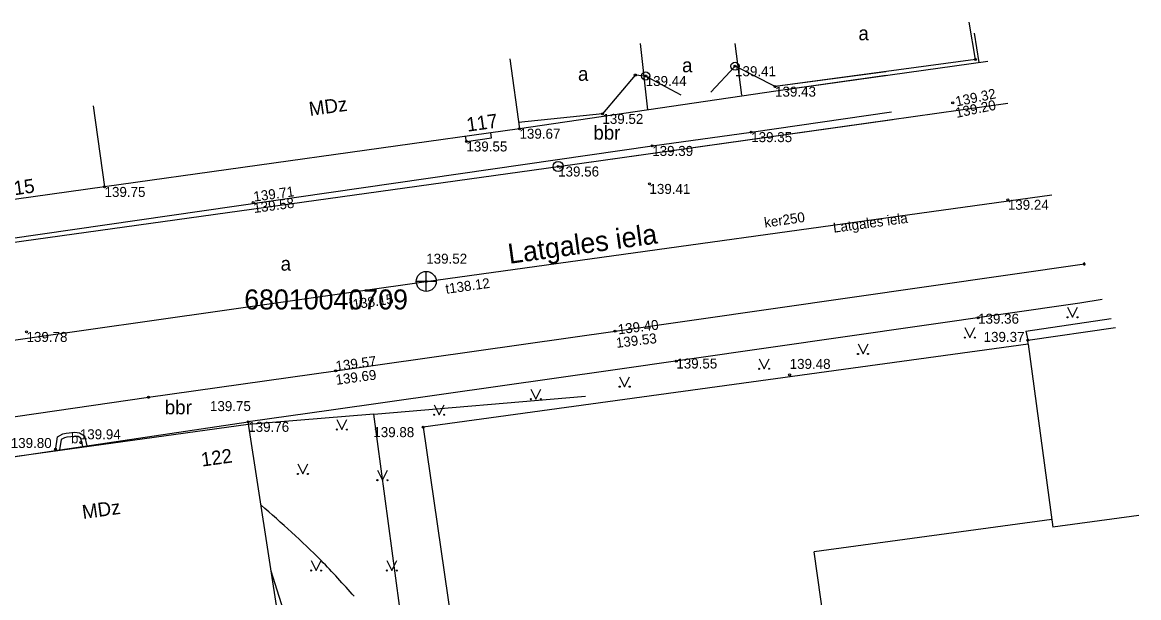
# Model space of a CAD drawing. Extents: x 728848 to 728956, y 273098 to 273185.
# Drawn here: x 728884.3 to 728940.1, y 273155.9 to 273184.7 of the extents above; entities that cross this region are included whole.
import ezdxf

# ---------------------------------------------------------------- set-up
doc = ezdxf.new("R2010")
doc.units = 0
for name, color, linetype in [('BUVE_BDET_####_####_#', 7, 'Continuous'), ('BUVE_BDET_####_TKST_#', 7, 'Continuous'), ('BUVE_EKAS_####_####_#', 7, 'Continuous'), ('BUVE_EKAS_ADRS_TKST_#', 7, 'Continuous'), ('BUVE_EKAS_RAKS_TKST_#', 7, 'Continuous'), ('CELI_CAPM_####_####_#', 7, 'Continuous'), ('CELI_CMAL_####_####_#', 7, 'Continuous'), ('CELI_CSEG_####_TKST_#', 7, 'Continuous'), ('CELI_IELA_####_TKST_#', 7, 'Continuous'), ('ELEK_ELEM_####_####_#', 7, 'Continuous'), ('ELEK_VADV_ZSPR_####_#', 7, 'Continuous'), ('NORB_ELEM_####_####_#', 7, 'Continuous'), ('NORB_ZOGS_ZSTP_####_#', 7, 'Continuous'), ('RELJ_AATZ_####_TKST_#', 7, 'Continuous'), ('RELJ_ELEM_####_####_#', 7, 'Continuous'), ('RELJ_HORZ_RESN_####_#', 7, 'Continuous'), ('ROBZ_KADS_####_TKST_#', 7, 'Continuous'), ('ROBZ_UZMR_####_####_#', 7, 'Continuous'), ('SKAN_ELEM_####_####_#', 7, 'Continuous'), ('SKAN_ELEM_PAST_TKST_#', 7, 'Continuous'), ('SKAN_VADP_PAST_####_#', 7, 'Continuous'), ('SKAN_VADP_PAST_TKST_#', 7, 'Continuous'), ('TERT_ELEM_####_####_#', 7, 'Continuous')]:
    doc.layers.add(name, color=color, linetype=linetype)

msp = doc.modelspace()

# ---------------------------------------------------------------- linework, layer by layer
at = {"layer": 'BUVE_BDET_####_####_#'}
for p, q in [((728907.767, 273178.889), (728907.73, 273179.145)), ((728906.509, 273178.709), (728906.468, 273178.968)), ((728906.509, 273178.709), (728907.767, 273178.889))]:
    msp.add_line(p, q, dxfattribs=at)
for points in [[(728885.974, 273163.262), (728886.081, 273163.935), (728886.346, 273164.087), (728886.515, 273164.125), (728886.941, 273164.169), (728887.184, 273164.149), (728887.422, 273163.993), (728887.535, 273163.494)], [(728887.335, 273163.464), (728887.243, 273163.868), (728887.115, 273163.952), (728886.943, 273163.966), (728886.548, 273163.925), (728886.42, 273163.896), (728886.265, 273163.808), (728886.184, 273163.294)]]:
    msp.add_lwpolyline(points, dxfattribs=at)
at = {"layer": 'BUVE_EKAS_####_####_#'}
for p, q in [((728908.671, 273182.834), (728909.161, 273179.346)), ((728887.858, 273180.487), (728888.427, 273176.436)), ((728909.161, 273179.346), (728888.427, 273176.436)), ((728888.427, 273176.436), (728876.392, 273174.747)), ((728934.555, 273168.77), (728938.942, 273169.413)), ((728934.577, 273168.568), (728904.348, 273164.427)), ((728934.577, 273168.568), (728934.555, 273168.77)), ((728934.577, 273168.568), (728935.813, 273159.42)), ((728880.21, 273162.407), (728895.607, 273164.692)), ((728881.265, 273162.564), (728895.607, 273164.692)), ((728897.893, 273149.784), (728895.607, 273164.692)), ((728904.348, 273164.427), (728910.037, 273125.181)), ((728935.759, 273159.816), (728923.879, 273158.199)), ((728940.1, 273160.003), (728935.813, 273159.42)), ((728928.159, 273127.726), (728923.879, 273158.199))]:
    msp.add_line(p, q, dxfattribs=at)
at = {"layer": 'CELI_CAPM_####_####_#'}
for points in [[(728877.231, 273172.928), (728915.793, 273178.486), (728920.739, 273179.175), (728927.751, 273180.197)], [(728874.692, 273163.616), (728890.623, 273165.918), (728899.975, 273167.245), (728913.935, 273169.231), (728937.385, 273172.585), (728937.418, 273172.59)]]:
    msp.add_lwpolyline(points, dxfattribs=at)
at = {"layer": 'CELI_CMAL_####_####_#'}
msp.add_line((728934.468, 273169.221), (728938.73, 273169.854), dxfattribs=at)
for points in [[(728915.567, 273180.287), (728915.213, 273183.6)], [(728920.275, 273181.023), (728919.945, 273183.6)], [(728932.125, 273182.653), (728931.891, 273184.116)], [(728932.564, 273182.712), (728921.973, 273181.228), (728909.161, 273179.346)], [(728927.488, 273182.001), (728921.973, 273181.228), (728909.161, 273179.346)], [(728938.276, 273170.802), (728937.162, 273170.62), (728913.708, 273167.266), (728899.747, 273165.28), (728895.607, 273164.692)], [(728934.468, 273169.221), (728934.555, 273168.77)]]:
    msp.add_lwpolyline(points, dxfattribs=at)
at = {"layer": 'ELEK_ELEM_####_####_#'}
msp.add_circle((728911.092, 273177.457), 0.25, dxfattribs=at)
at = {"layer": 'ELEK_VADV_ZSPR_####_#'}
for p, q in [((728911.092, 273177.457), (728933.567, 273180.62)), ((728911.092, 273177.457), (728927.807, 273179.81)), ((728880.569, 273173.213), (728911.092, 273177.457)), ((728899.357, 273149.053), (728896.751, 273157.234))]:
    msp.add_line(p, q, dxfattribs=at)
at = {"layer": 'NORB_ELEM_####_####_#'}
for p, q in [((728919.931, 273182.471), (728918.718, 273181.177)), ((728915.467, 273181.981), (728917.23, 273181.048))]:
    msp.add_line(p, q, dxfattribs=at)
for centre in [(728919.931, 273182.471), (728915.467, 273181.981)]:
    msp.add_circle(centre, 0.202, dxfattribs=at)
at = {"layer": 'NORB_ZOGS_ZSTP_####_#'}
for points in [[(728931.95, 273182.807), (728931.628, 273184.665)], [(728931.95, 273182.807), (728921.93, 273181.449), (728919.931, 273182.471)], [(728927.46, 273182.198), (728921.93, 273181.449), (728919.931, 273182.471)], [(728915.467, 273181.981), (728914.949, 273182.03), (728913.303, 273180.087), (728909.117, 273179.656)]]:
    msp.add_lwpolyline(points, dxfattribs=at)
at = {"layer": 'RELJ_ELEM_####_####_#'}
msp.add_line((728937.431, 273172.564), (728937.398, 273172.634), dxfattribs=at)
for centre in [(728919.931, 273182.471), (728931.95, 273182.807), (728914.949, 273182.03), (728915.467, 273181.981), (728921.93, 273181.449), (728930.806, 273180.643), (728913.303, 273180.087), (728909.161, 273179.346), (728920.739, 273179.175), (728906.509, 273178.709), (728915.793, 273178.486), (728911.092, 273177.457), (728888.427, 273176.436), (728915.655, 273176.587), (728933.561, 273175.793), (728895.854, 273175.652), (728904.501, 273171.712), (728932.075, 273169.9), (728884.528, 273169.186), (728913.935, 273169.231), (728934.555, 273168.77), (728916.997, 273167.728), (728899.975, 273167.244), (728922.66, 273167.047), (728890.623, 273165.918), (728895.607, 273164.692), (728904.348, 273164.427), (728887.249, 273163.653), (728885.976, 273163.322)]:
    msp.add_circle(centre, 0.05, dxfattribs=at)
msp.add_arc((728937.385, 273172.585), 0.05, 75.7175, 335.5242, dxfattribs=at)
at = {"layer": 'RELJ_HORZ_RESN_####_#'}
msp.add_spline([(728900.901, 273155.972), (728899.249, 273157.759), (728896.246, 273160.527)], degree=3, dxfattribs=at)
at = {"layer": 'ROBZ_UZMR_####_####_#'}
msp.add_line((728895.601, 273164.553), (728880.25, 273162.441), dxfattribs=at)
for points in [[(728901.876, 273165.08), (728912.452, 273165.969)], [(728902.844, 273122.265), (728906.58, 273122.86), (728903.634, 273144.437), (728904.623, 273144.571), (728901.876, 273165.08), (728895.601, 273164.553)]]:
    msp.add_lwpolyline(points, dxfattribs=at)
at = {"layer": 'SKAN_ELEM_####_####_#'}
for p, q in [((728904.501, 273171.212), (728904.501, 273172.212)), ((728905.001, 273171.712), (728904.001, 273171.712))]:
    msp.add_line(p, q, dxfattribs=at)
msp.add_circle((728904.501, 273171.712), 0.5, dxfattribs=at)
at = {"layer": 'SKAN_VADP_PAST_####_#'}
msp.add_lwpolyline([(728874.023, 273167.371), (728904.501, 273171.712), (728935.767, 273176.034)], dxfattribs=at)
at = {"layer": 'TERT_ELEM_####_####_#'}
for p, q in [((728936.547, 273170.417), (728936.797, 273169.917)), ((728936.797, 273169.917), (728937.047, 273170.417)), ((728931.409, 273169.404), (728931.659, 273168.904)), ((728931.659, 273168.904), (728931.909, 273169.404)), ((728926.077, 273168.586), (728926.327, 273168.086)), ((728926.327, 273168.086), (728926.577, 273168.586)), ((728921.133, 273167.846), (728921.383, 273167.346)), ((728921.383, 273167.346), (728921.633, 273167.846)), ((728914.166, 273166.95), (728914.416, 273166.45)), ((728914.416, 273166.45), (728914.666, 273166.95)), ((728909.729, 273166.326), (728909.979, 273165.826)), ((728909.979, 273165.826), (728910.229, 273166.326)), ((728904.902, 273165.547), (728905.152, 273165.047)), ((728905.152, 273165.047), (728905.402, 273165.547)), ((728900.037, 273164.807), (728900.287, 273164.307)), ((728900.287, 273164.307), (728900.537, 273164.807)), ((728898.09, 273162.586), (728898.34, 273162.086)), ((728898.34, 273162.086), (728898.59, 273162.586)), ((728902.061, 273162.275), (728902.311, 273161.775)), ((728902.311, 273161.775), (728902.561, 273162.275)), ((728898.749, 273157.759), (728898.999, 273157.259)), ((728898.999, 273157.259), (728899.249, 273157.759)), ((728902.531, 273157.759), (728902.781, 273157.259)), ((728902.781, 273157.259), (728903.031, 273157.759))]:
    msp.add_line(p, q, dxfattribs=at)
for centre, radius in [((728936.547, 273169.917), 0.028), ((728937.047, 273169.917), 0.0263), ((728931.409, 273168.904), 0.028), ((728931.909, 273168.904), 0.0263), ((728926.076, 273168.086), 0.028), ((728926.576, 273168.086), 0.0263), ((728921.133, 273167.345), 0.028), ((728921.633, 273167.345), 0.0263), ((728914.166, 273166.449), 0.028), ((728914.666, 273166.449), 0.0263), ((728909.728, 273165.826), 0.028), ((728910.228, 273165.826), 0.0263), ((728904.902, 273165.047), 0.028), ((728905.402, 273165.047), 0.0263), ((728900.036, 273164.307), 0.028), ((728900.536, 273164.307), 0.0263), ((728898.09, 273162.086), 0.028), ((728898.59, 273162.086), 0.0263), ((728902.06, 273161.774), 0.028), ((728902.56, 273161.774), 0.0263), ((728898.748, 273157.259), 0.028), ((728899.248, 273157.259), 0.0263), ((728902.531, 273157.259), 0.028), ((728903.031, 273157.259), 0.0263)]:
    msp.add_circle(centre, radius, dxfattribs=at)

# ---------------------------------------------------------------- texts
at = {"layer": 'BUVE_BDET_####_TKST_#'}
msp.add_text('b', height=0.5, dxfattribs=at).set_placement((728886.749, 273163.619))
at = {"layer": 'BUVE_EKAS_ADRS_TKST_#'}
for s, rotation, p in [('117', 7.9892, (728906.565, 273179.194)), ('115', 7.9888, (728883.422, 273175.946)), ('122', 7.8336, (728893.298, 273162.453))]:
    msp.add_text(s, height=0.7, rotation=rotation, dxfattribs=at).set_placement(p)
at = {"layer": 'BUVE_EKAS_RAKS_TKST_#'}
for p in [(728898.691, 273179.98), (728887.356, 273159.829)]:
    msp.add_text('MDz', height=0.7, rotation=7.9888, dxfattribs=at).set_placement(p)
at = {"layer": 'CELI_CSEG_####_TKST_#'}
for s, p in [('a', (728926.095, 273183.768)), ('a', (728917.283, 273182.171)), ('a', (728912.083, 273181.742)), ('bbr', (728912.852, 273178.799)), ('a', (728897.225, 273172.249)), ('bbr', (728891.437, 273165.069))]:
    msp.add_text(s, height=0.7, dxfattribs=at).set_placement(p)
at = {"layer": 'CELI_IELA_####_TKST_#'}
for height, rotation, p in [(0.5, 7.6516, (728924.864, 273174.146)), (1, 7.8699, (728908.656, 273172.589))]:
    msp.add_text('Latgales iela', height=height, rotation=rotation, dxfattribs=at).set_placement(p)
at = {"layer": 'RELJ_AATZ_####_TKST_#'}
for s, p in [('139.41', (728919.931, 273181.971)), ('139.44', (728915.467, 273181.481)), ('139.43', (728921.93, 273180.949)), ('139.52', (728913.303, 273179.587)), ('139.67', (728909.161, 273178.846)), ('139.35', (728920.739, 273178.675)), ('139.55', (728906.509, 273178.209)), ('139.39', (728915.793, 273177.986)), ('139.56', (728911.092, 273176.957)), ('139.75', (728888.427, 273175.936)), ('139.41', (728915.655, 273176.087)), ('139.24', (728933.561, 273175.293)), ('139.36', (728932.075, 273169.598)), ('139.78', (728884.528, 273168.686)), ('139.37', (728932.351, 273168.689)), ('139.55', (728916.997, 273167.358)), ('139.48', (728922.66, 273167.339)), ('139.75', (728893.694, 273165.23)), ('139.76', (728895.607, 273164.192)), ('139.94', (728887.191, 273163.821)), ('139.88', (728901.857, 273163.927)), ('139.80', (728883.741, 273163.385))]:
    msp.add_text(s, height=0.5, dxfattribs=at).set_placement(p)
for s, rotation, p in [('139.32', 11.8186, (728931.002, 273180.455)), ('139.20', 11.8186, (728931.002, 273179.885)), ('139.71', 7.6596, (728895.905, 273175.7)), ('139.58', 7.6596, (728895.905, 273175.129)), ('139.40', 6.9257, (728914.107, 273169.063)), ('139.53', 6.9257, (728914.012, 273168.387)), ('139.57', 7.6575, (728900.009, 273167.221)), ('139.69', 7.6575, (728900.009, 273166.538))]:
    msp.add_text(s, height=0.5, rotation=rotation, dxfattribs=at).set_placement(p)
at = {"layer": 'ROBZ_KADS_####_TKST_#'}
msp.add_text('68010040709', height=1, dxfattribs=at).set_placement((728895.406, 273170.312))
at = {"layer": 'SKAN_ELEM_PAST_TKST_#'}
msp.add_text('139.52', height=0.5, dxfattribs=at).set_placement((728904.501, 273172.598))
at = {"layer": 'SKAN_VADP_PAST_TKST_#'}
for s, rotation, p in [('ker250', 8.258, (728921.425, 273174.399)), ('t138.12', 7.8699, (728905.499, 273171.089)), ('t138.15', 8.1064, (728900.683, 273170.288))]:
    msp.add_text(s, height=0.5, rotation=rotation, dxfattribs=at).set_placement(p)

doc.saveas('drawing.dxf')
